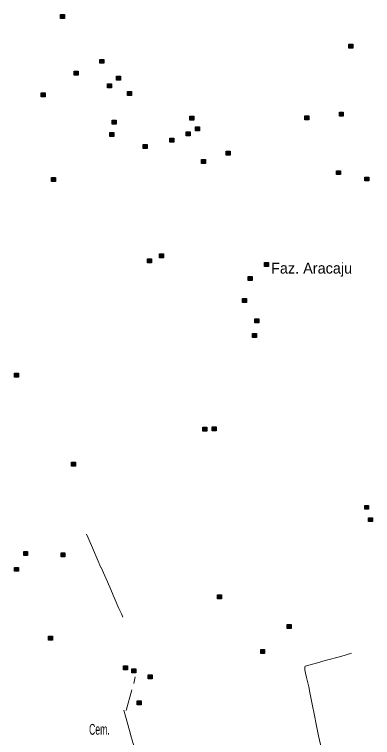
# Model space of a CAD drawing. Extents: x 393.5 to 446.9, y 8064.8 to 8120.4.
# Drawn here: x 394.11 to 399.42, y 8098.67 to 8109.38 of the extents above; entities that cross this region are included whole.
import ezdxf

# ---------------------------------------------------------------- set-up
doc = ezdxf.new("R2010")
doc.units = 0
doc.header["$LTSCALE"] = 0.064
doc.linetypes.add('DOT_DASHED', pattern=[7.7, 5, -1.2, 0.3, -1.2])
doc.layers.add('2', color=7, linetype='Continuous', lineweight=25)
doc.layers.add('22', color=7, linetype='DOT_DASHED', lineweight=13)
doc.layers.add('61', color=7, linetype='Continuous')

msp = doc.modelspace()

# ---------------------------------------------------------------- hatches: boundary and pattern name
at = {"layer": '2'}
for points in [[(394.7951, 8109.3783), (394.8531, 8109.3783), (394.8531, 8109.3203), (394.7951, 8109.3203)], [(399.0645, 8108.9368), (399.1225, 8108.9368), (399.1225, 8108.8788), (399.0645, 8108.8788)], [(395.3795, 8108.7134), (395.4375, 8108.7134), (395.4375, 8108.6554), (395.3795, 8108.6554)], [(394.9988, 8108.5385), (395.0568, 8108.5385), (395.0568, 8108.4805), (394.9988, 8108.4805)], [(395.6259, 8108.4656), (395.6839, 8108.4656), (395.6839, 8108.4076), (395.6259, 8108.4076)], [(395.4924, 8108.3491), (395.5504, 8108.3491), (395.5504, 8108.2911), (395.4924, 8108.2911)], [(394.5104, 8108.2159), (394.5684, 8108.2159), (394.5684, 8108.1579), (394.5104, 8108.1579)], [(395.788, 8108.2371), (395.846, 8108.2371), (395.846, 8108.1791), (395.788, 8108.1791)], [(398.926, 8107.9291), (398.984, 8107.9291), (398.984, 8107.8711), (398.926, 8107.8711)], [(396.7121, 8107.8714), (396.7701, 8107.8714), (396.7701, 8107.8134), (396.7121, 8107.8134)], [(398.4141, 8107.8765), (398.4721, 8107.8765), (398.4721, 8107.8185), (398.4141, 8107.8185)], [(395.5593, 8107.8138), (395.6173, 8107.8138), (395.6173, 8107.7558), (395.5593, 8107.7558)], [(396.7949, 8107.7152), (396.8529, 8107.7152), (396.8529, 8107.6572), (396.7949, 8107.6572)], [(395.526, 8107.6293), (395.584, 8107.6293), (395.584, 8107.5713), (395.526, 8107.5713)], [(396.6583, 8107.6393), (396.7163, 8107.6393), (396.7163, 8107.5813), (396.6583, 8107.5813)], [(396.4146, 8107.5468), (396.4726, 8107.5468), (396.4726, 8107.4888), (396.4146, 8107.4888)], [(396.0203, 8107.4509), (396.0783, 8107.4509), (396.0783, 8107.3929), (396.0203, 8107.3929)], [(397.2501, 8107.3547), (397.3081, 8107.3547), (397.3081, 8107.2967), (397.2501, 8107.2967)], [(396.8848, 8107.2286), (396.9428, 8107.2286), (396.9428, 8107.1706), (396.8848, 8107.1706)], [(394.6607, 8106.9623), (394.7187, 8106.9623), (394.7187, 8106.9043), (394.6607, 8106.9043)], [(398.8836, 8107.0642), (398.9416, 8107.0642), (398.9416, 8107.0062), (398.8836, 8107.0062)], [(399.3033, 8106.9709), (399.3613, 8106.9709), (399.3613, 8106.9129), (399.3033, 8106.9129)], [(396.2617, 8105.8336), (396.3197, 8105.8336), (396.3197, 8105.7756), (396.2617, 8105.7756)], [(396.0832, 8105.7602), (396.1412, 8105.7602), (396.1412, 8105.7022), (396.0832, 8105.7022)], [(397.8156, 8105.7043), (397.8736, 8105.7043), (397.8736, 8105.6463), (397.8156, 8105.6463)], [(397.5752, 8105.4976), (397.6332, 8105.4976), (397.6332, 8105.4396), (397.5752, 8105.4396)], [(397.4906, 8105.1731), (397.5486, 8105.1731), (397.5486, 8105.1151), (397.4906, 8105.1151)], [(397.6738, 8104.8695), (397.7318, 8104.8695), (397.7318, 8104.8115), (397.6738, 8104.8115)], [(397.6408, 8104.6516), (397.6988, 8104.6516), (397.6988, 8104.5936), (397.6408, 8104.5936)], [(394.114, 8104.0673), (394.172, 8104.0673), (394.172, 8104.0093), (394.114, 8104.0093)], [(396.9034, 8103.2651), (396.9614, 8103.2651), (396.9614, 8103.2071), (396.9034, 8103.2071)], [(397.0427, 8103.2719), (397.1007, 8103.2719), (397.1007, 8103.2139), (397.0427, 8103.2139)], [(394.9602, 8102.7468), (395.0182, 8102.7468), (395.0182, 8102.6888), (394.9602, 8102.6888)], [(399.3001, 8102.1081), (399.3581, 8102.1081), (399.3581, 8102.0501), (399.3001, 8102.0501)], [(399.3587, 8101.9256), (399.4167, 8101.9256), (399.4167, 8101.8676), (399.3587, 8101.8676)], [(394.2506, 8101.4263), (394.3086, 8101.4263), (394.3086, 8101.3683), (394.2506, 8101.3683)], [(394.8025, 8101.4054), (394.8605, 8101.4054), (394.8605, 8101.3474), (394.8025, 8101.3474)], [(394.1131, 8101.1897), (394.1711, 8101.1897), (394.1711, 8101.1317), (394.1131, 8101.1317)], [(397.1217, 8100.7835), (397.1797, 8100.7835), (397.1797, 8100.7255), (397.1217, 8100.7255)], [(398.1524, 8100.3453), (398.2104, 8100.3453), (398.2104, 8100.2873), (398.1524, 8100.2873)], [(394.6183, 8100.1725), (394.6763, 8100.1725), (394.6763, 8100.1145), (394.6183, 8100.1145)], [(397.7609, 8099.9745), (397.8189, 8099.9745), (397.8189, 8099.9165), (397.7609, 8099.9165)], [(395.7302, 8099.7332), (395.7882, 8099.7332), (395.7882, 8099.6752), (395.7302, 8099.6752)], [(395.8524, 8099.6854), (395.9104, 8099.6854), (395.9104, 8099.6274), (395.8524, 8099.6274)], [(396.0936, 8099.6), (396.1516, 8099.6), (396.1516, 8099.542), (396.0936, 8099.542)], [(395.9298, 8099.2125), (395.9878, 8099.2125), (395.9878, 8099.1545), (395.9298, 8099.1545)]]:
    msp.add_hatch(color=256, dxfattribs=at).paths.add_polyline_path(points)

# ---------------------------------------------------------------- linework, layer by layer
for points in [[(394.7951, 8109.3783), (394.8531, 8109.3783), (394.8531, 8109.3203), (394.7951, 8109.3203)], [(399.0645, 8108.9368), (399.1225, 8108.9368), (399.1225, 8108.8788), (399.0645, 8108.8788)], [(395.3795, 8108.7134), (395.4375, 8108.7134), (395.4375, 8108.6554), (395.3795, 8108.6554)], [(394.9988, 8108.5385), (395.0568, 8108.5385), (395.0568, 8108.4805), (394.9988, 8108.4805)], [(395.6259, 8108.4656), (395.6839, 8108.4656), (395.6839, 8108.4076), (395.6259, 8108.4076)], [(395.4924, 8108.3491), (395.5504, 8108.3491), (395.5504, 8108.2911), (395.4924, 8108.2911)], [(394.5104, 8108.2159), (394.5684, 8108.2159), (394.5684, 8108.1579), (394.5104, 8108.1579)], [(395.788, 8108.2371), (395.846, 8108.2371), (395.846, 8108.1791), (395.788, 8108.1791)], [(398.926, 8107.9291), (398.984, 8107.9291), (398.984, 8107.8711), (398.926, 8107.8711)], [(396.7121, 8107.8714), (396.7701, 8107.8714), (396.7701, 8107.8134), (396.7121, 8107.8134)], [(398.4141, 8107.8765), (398.4721, 8107.8765), (398.4721, 8107.8185), (398.4141, 8107.8185)], [(395.5593, 8107.8138), (395.6173, 8107.8138), (395.6173, 8107.7558), (395.5593, 8107.7558)], [(396.7949, 8107.7152), (396.8529, 8107.7152), (396.8529, 8107.6572), (396.7949, 8107.6572)], [(395.526, 8107.6293), (395.584, 8107.6293), (395.584, 8107.5713), (395.526, 8107.5713)], [(396.6583, 8107.6393), (396.7163, 8107.6393), (396.7163, 8107.5813), (396.6583, 8107.5813)], [(396.4146, 8107.5468), (396.4726, 8107.5468), (396.4726, 8107.4888), (396.4146, 8107.4888)], [(396.0203, 8107.4509), (396.0783, 8107.4509), (396.0783, 8107.3929), (396.0203, 8107.3929)], [(397.2501, 8107.3547), (397.3081, 8107.3547), (397.3081, 8107.2967), (397.2501, 8107.2967)], [(396.8848, 8107.2286), (396.9428, 8107.2286), (396.9428, 8107.1706), (396.8848, 8107.1706)], [(394.6607, 8106.9623), (394.7187, 8106.9623), (394.7187, 8106.9043), (394.6607, 8106.9043)], [(398.8836, 8107.0642), (398.9416, 8107.0642), (398.9416, 8107.0062), (398.8836, 8107.0062)], [(399.3033, 8106.9709), (399.3613, 8106.9709), (399.3613, 8106.9129), (399.3033, 8106.9129)], [(396.2617, 8105.8336), (396.3197, 8105.8336), (396.3197, 8105.7756), (396.2617, 8105.7756)], [(396.0832, 8105.7602), (396.1412, 8105.7602), (396.1412, 8105.7022), (396.0832, 8105.7022)], [(397.8156, 8105.7043), (397.8736, 8105.7043), (397.8736, 8105.6463), (397.8156, 8105.6463)], [(397.5752, 8105.4976), (397.6332, 8105.4976), (397.6332, 8105.4396), (397.5752, 8105.4396)], [(397.4906, 8105.1731), (397.5486, 8105.1731), (397.5486, 8105.1151), (397.4906, 8105.1151)], [(397.6738, 8104.8695), (397.7318, 8104.8695), (397.7318, 8104.8115), (397.6738, 8104.8115)], [(397.6408, 8104.6516), (397.6988, 8104.6516), (397.6988, 8104.5936), (397.6408, 8104.5936)], [(394.114, 8104.0673), (394.172, 8104.0673), (394.172, 8104.0093), (394.114, 8104.0093)], [(396.9034, 8103.2651), (396.9614, 8103.2651), (396.9614, 8103.2071), (396.9034, 8103.2071)], [(397.0427, 8103.2719), (397.1007, 8103.2719), (397.1007, 8103.2139), (397.0427, 8103.2139)], [(394.9602, 8102.7468), (395.0182, 8102.7468), (395.0182, 8102.6888), (394.9602, 8102.6888)], [(399.3001, 8102.1081), (399.3581, 8102.1081), (399.3581, 8102.0501), (399.3001, 8102.0501)], [(399.3587, 8101.9256), (399.4167, 8101.9256), (399.4167, 8101.8676), (399.3587, 8101.8676)], [(394.2506, 8101.4263), (394.3086, 8101.4263), (394.3086, 8101.3683), (394.2506, 8101.3683)], [(394.8025, 8101.4054), (394.8605, 8101.4054), (394.8605, 8101.3474), (394.8025, 8101.3474)], [(394.1131, 8101.1897), (394.1711, 8101.1897), (394.1711, 8101.1317), (394.1131, 8101.1317)], [(397.1217, 8100.7835), (397.1797, 8100.7835), (397.1797, 8100.7255), (397.1217, 8100.7255)], [(398.1524, 8100.3453), (398.2104, 8100.3453), (398.2104, 8100.2873), (398.1524, 8100.2873)], [(394.6183, 8100.1725), (394.6763, 8100.1725), (394.6763, 8100.1145), (394.6183, 8100.1145)], [(397.7609, 8099.9745), (397.8189, 8099.9745), (397.8189, 8099.9165), (397.7609, 8099.9165)], [(395.7302, 8099.7332), (395.7882, 8099.7332), (395.7882, 8099.6752), (395.7302, 8099.6752)], [(395.8524, 8099.6854), (395.9104, 8099.6854), (395.9104, 8099.6274), (395.8524, 8099.6274)], [(396.0936, 8099.6), (396.1516, 8099.6), (396.1516, 8099.542), (396.0936, 8099.542)], [(395.9298, 8099.2125), (395.9878, 8099.2125), (395.9878, 8099.1545), (395.9298, 8099.1545)]]:
    msp.add_lwpolyline(points, close=True, dxfattribs=at)
at = {"layer": '22'}
for points in [[(395.7206, 8100.4543), (395.6962, 8100.5013), (395.6614, 8100.583), (395.59, 8100.7448), (395.5274, 8100.8961), (395.3943, 8101.1895), (395.2818, 8101.4434), (395.2024, 8101.628), (395.1798, 8101.6819)], [(398.6812, 8098.3934), (398.6761, 8098.4112), (398.6473, 8098.5648), (398.6161, 8098.6962), (398.5816, 8098.8661), (398.5547, 8098.9964), (398.5233, 8099.1623), (398.4902, 8099.3367), (398.4723, 8099.4223), (398.4405, 8099.5569), (398.4226, 8099.6233), (398.4136, 8099.6731), (398.4136, 8099.7127), (398.4175, 8099.7293), (398.4737, 8099.7421), (398.6028, 8099.7778), (398.7153, 8099.8098), (398.9486, 8099.8724), (399.1046, 8099.9184)], [(395.7667, 8099.0688), (395.8807, 8099.4714), (395.9029, 8099.5682)], [(395.9576, 8098.2726), (395.8857, 8098.5332), (395.8434, 8098.6804), (395.8192, 8098.7751), (395.7577, 8098.9847), (395.7355, 8099.0734)]]:
    msp.add_lwpolyline(points, dxfattribs=at)

# ---------------------------------------------------------------- texts
at = {"layer": '61'}
msp.add_text('Faz. Aracaju', height=0.16, dxfattribs=at).set_placement((397.9137, 8105.5415))
at = {"layer": '61', "width": 0.6}
msp.add_text('Cem.', height=0.16, dxfattribs=at).set_placement((395.2182, 8098.7118))

doc.saveas('drawing.dxf')
